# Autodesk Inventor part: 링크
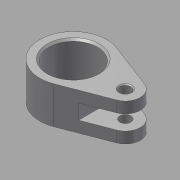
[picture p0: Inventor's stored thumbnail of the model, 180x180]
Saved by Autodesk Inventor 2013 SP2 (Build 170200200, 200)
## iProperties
Created: 2015-12
Part Number: 링크
Material: 강철, 연강
Document SubType Name: Modeling
Designer: mduedu
Density: 7.86 g/cm^3
Author: mduedu
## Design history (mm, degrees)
sketch "스케치1"
  geometry: L1 (6.429, -16.813)-(30.857, -7.472); L2 (6.429, 16.813)-(30.857, 7.472); A1 r 18 centre (0, 0) between (6.429, 16.813) and (6.429, -16.813); A2 r 8 centre (28, 0) between (30.857, -7.472) and (30.857, 7.472); 1 further point
  constraints: 4 end point, 4 point on circle, 4 tangent, 2 centre point, 1 coincident, 1 horizontal alignment
  dimensions: "d0" = 18 radius of A1; "d1" = 8 radius of A2; "d2" = 28 distance of A2.centre point (0, 0)
extrude "돌출1" new body sketch "스케치1" stored distance "d3" = 20; taper "d4" = 0 deg
sketch "스케치2"
  geometry: L1 (6.429, 16.813)-(30.857, 7.472) reference; L2 (30.857, -7.472)-(6.429, -16.813) reference; L3 (16, 13.153)-(16, -13.153); A1 r 8 centre (28, 0) between (30.857, -7.472) and (30.857, 7.472) reference; 1 further point
  constraints: 2 end point, 2 point on line, 1 vertical
  dimensions: "d5" = 20 dimension on A1 L3
extrude "돌출2" cut sketch "스케치2" stored distance "d6" = 8; taper "d7" = 0 deg
hole "구멍1" diameter "d10" = 26; stored, may be unused: countersink angle "d14" = 90 deg, drill point angle "d16" = 118 deg; dims "d8" = 10, "d9" = 10, "d11" = 6, "d12" = 4, "d13" = 2, "d15" = 8
hole "구멍2" diameter "d19" = 6; stored, may be unused: countersink angle "d23" = 90 deg, drill point angle "d25" = 118 deg; dims "d20" = 6, "d21" = 4, "d22" = 2, "d24" = 8, "d32" = 10, "d33" = 10
chamfer "모따기1" distance "d26" = 1; stored, may be unused: second distance "d27" = 2, angle "d28" = 45 deg
chamfer "모따기2" distance "d29" = 0.5; stored, may be unused: second distance "d30" = 2, angle "d31" = 45 deg
node "솔리드1"
